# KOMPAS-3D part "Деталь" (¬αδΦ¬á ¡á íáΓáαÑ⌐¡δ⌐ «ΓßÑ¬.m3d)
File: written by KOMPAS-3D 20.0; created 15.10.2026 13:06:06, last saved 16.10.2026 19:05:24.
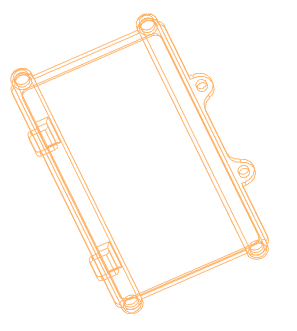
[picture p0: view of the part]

Document properties: Полное имя файла: D:\myProjects\Progect_esp32\box_compas\корпус\крышка на батарейный отсек.m3d

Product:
- Part/product: Деталь
    Масса: 0.0766137

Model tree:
1. Эскиз:1
2. Элемент выдавливания:1
     Расстояние 1 = 0.75
3. Эскиз:2  (with: Элемент выдавливания:1)
4. Элемент выдавливания:2
     Расстояние 1 = 3
5. Эскиз:3  (with: Элемент выдавливания:1, Элемент выдавливания:5, Элемент выдавливания:6, Скругление:2, Элемент выдавливания:26, Скругление:8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)
6. Эскиз:4  (with: Элемент выдавливания:1)
7. Элемент выдавливания:3
     Расстояние 1 = 1.5
8. Эскиз:5  (with: Элемент выдавливания:3)
9. Элемент выдавливания:4
     Расстояние 1 = 2
10. Скругление:2  (with: Элемент выдавливания:4, Элемент выдавливания:3)
     Радиус = 1
11. Эскиз:6  (with: Элемент выдавливания:2)
12. Элемент выдавливания:5
     Расстояние 2 = 3
13. Эскиз:7  (with: Элемент выдавливания:2, Элемент выдавливания:1, Скругление:1, Фаска:1)
14. Эскиз:8  (with: Элемент выдавливания:2, Элемент выдавливания:5)
15. Элемент выдавливания:6
     Расстояние 2 = 1.5
16. Скругление:11  (with: Элемент выдавливания:2)
     Радиус = 1
17. Скругление:12  (with: Элемент выдавливания:2)
     Радиус = 2
18. Скругление:14  (with: Элемент выдавливания:2)
     Радиус = 4
19. Эскиз:9  (with: Элемент выдавливания:1, Элемент выдавливания:5)
20. Элемент выдавливания:7
     Расстояние 2 = 2.5
21. Скругление:16  (with: Элемент выдавливания:1)
     Радиус = 2
22. Фаска:1  (with: Элемент выдавливания:7)
     Угол = 45; Длина 1 = 0.5; Длина 2 = 0.5

Referenced files in D:\myProjects\Progect_esp32\box_compas\сборки компонентов\: Back_Panel_Сборка_v2.a3d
